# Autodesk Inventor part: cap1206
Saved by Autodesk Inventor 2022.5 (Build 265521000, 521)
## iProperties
Created: 2024-12
Part Number: cap1206
Material: Generic
Document SubType Name: Modeling
Designer: AdminForWorker
Density: 1 g/cm^3
Appearance: Default
Title: cap1206 v1
Author: AdminForWorker
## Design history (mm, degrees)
feature "Body6"
feature "Body8"
feature "Body21"
body "Solid1"
body "Solid2"
body "Solid3"
